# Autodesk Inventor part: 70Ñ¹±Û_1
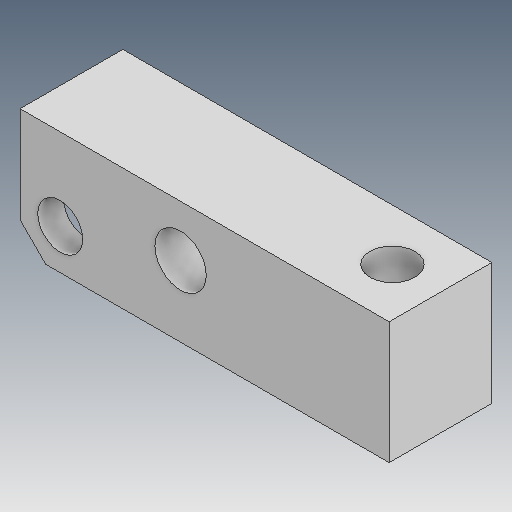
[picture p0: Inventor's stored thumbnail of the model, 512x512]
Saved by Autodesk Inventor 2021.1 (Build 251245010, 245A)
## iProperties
Created: 2019-04
Part Number: 70Ñ¹±Û_1
Material: Ogólny
Document SubType Name: Modeling
Designer: user
Density: 1 g/cm^3
Appearance: Domyślna
Author: user
Revision Number: ÈÎºÎ
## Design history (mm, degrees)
feature "ÊäÈë1"
node "Bryła1"
